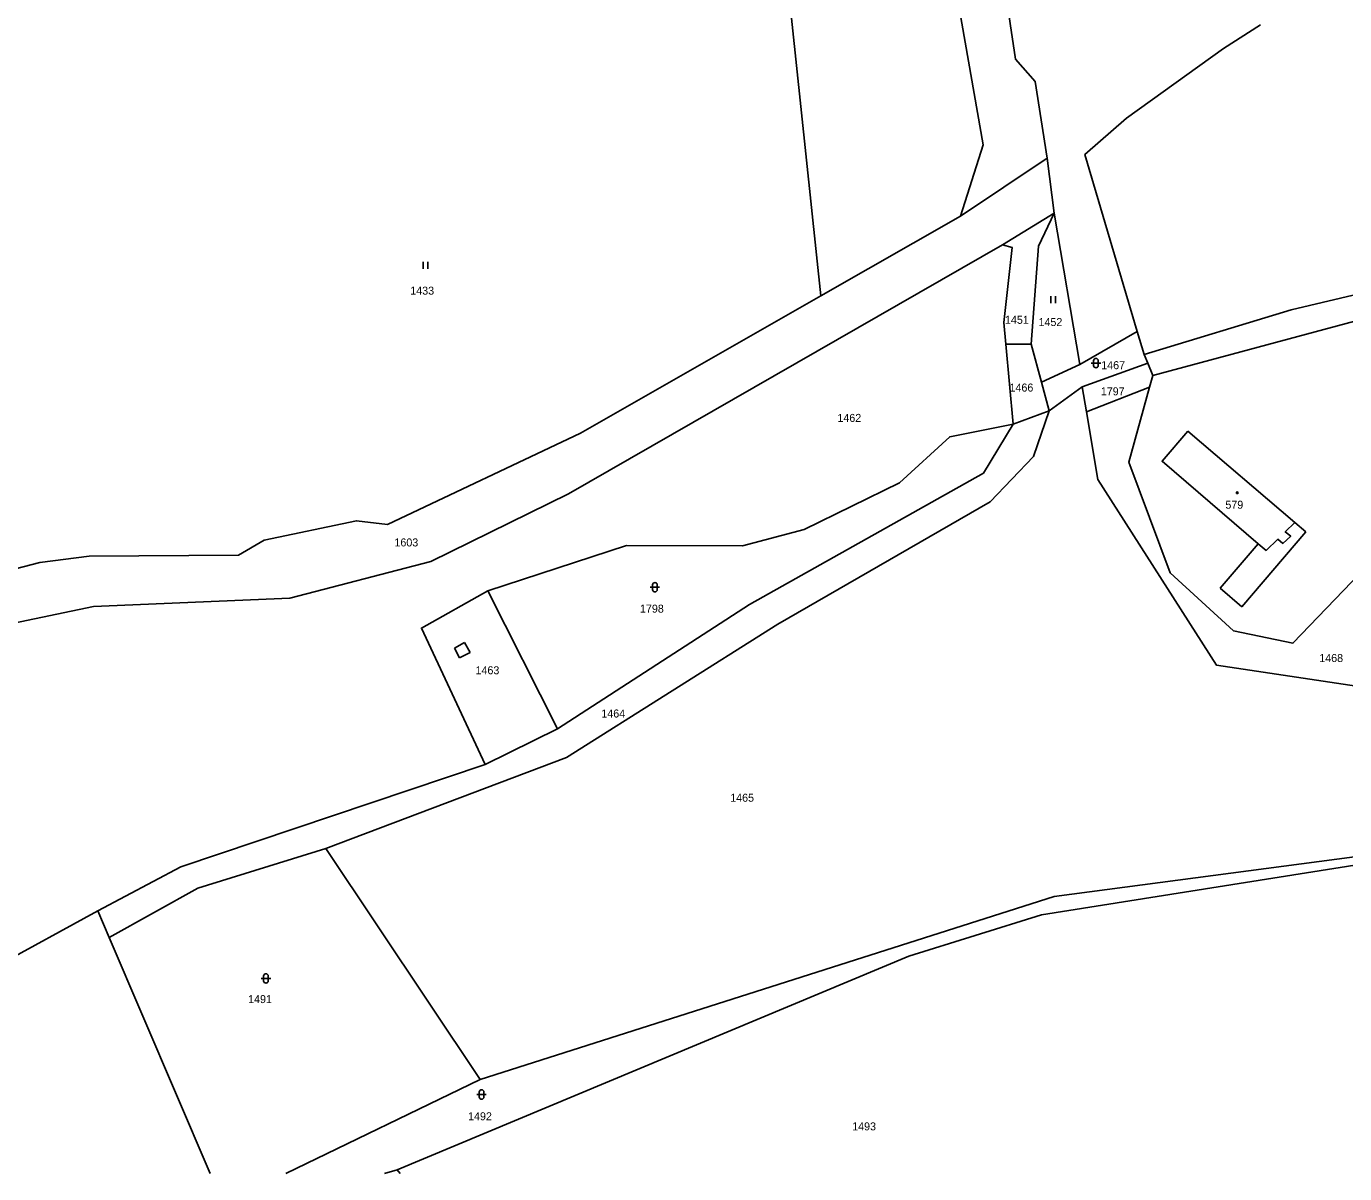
# Model space of a CAD drawing. Extents: x -520431 to -517205, y -1075927 to -1074013.
# Drawn here: x -518324.2 to -518044.1, y -1075925.4 to -1075681.5 of the extents above; entities that cross this region are included whole.
import ezdxf

# ---------------------------------------------------------------- set-up
doc = ezdxf.new("R2010")
doc.units = 0
for name, color, linetype in [('Hranice parcel', 7, 'Continuous'), ('Parcelní čísla', 7, 'Continuous'), ('Vnitřní kresba', 7, 'Continuous'), ('Značky budov', 7, 'Continuous'), ('Značky kultur', 7, 'Continuous')]:
    doc.layers.add(name, color=color, linetype=linetype)

msp = doc.modelspace()

# ---------------------------------------------------------------- linework, layer by layer
at = {"layer": 'Hranice parcel'}
for p, q in [((-518125.69, -1075721.88), (-518107.27, -1075709.57)), ((-518107.27, -1075709.57), (-518105.79, -1075721.22)), ((-518155.35, -1075738.81), (-518125.69, -1075721.88)), ((-518105.79, -1075721.22), (-518116.8, -1075727.96)), ((-518105.79, -1075721.22), (-518100.35, -1075753.39)), ((-518100.35, -1075753.39), (-518088.14, -1075746.39)), ((-518088.14, -1075746.39), (-518086.69, -1075751.28)), ((-518116.08, -1075749.11), (-518110.69, -1075749.06)), ((-518114.49, -1075766.06), (-518116.08, -1075749.11)), ((-518110.69, -1075749.06), (-518108.51, -1075757.18)), ((-518086.69, -1075751.28), (-518085.91, -1075753.13)), ((-518108.51, -1075757.18), (-518100.35, -1075753.39)), ((-518099.83, -1075758.13), (-518085.91, -1075753.13)), ((-518085.91, -1075753.13), (-518084.83, -1075755.71)), ((-518084.83, -1075755.71), (-518085.54, -1075758.24)), ((-518106.88, -1075763.27), (-518108.51, -1075757.18)), ((-518099.83, -1075758.13), (-518106.88, -1075763.27)), ((-518098.94, -1075763.48), (-518099.83, -1075758.13)), ((-518085.54, -1075758.24), (-518098.94, -1075763.48)), ((-518106.88, -1075763.27), (-518114.49, -1075766.06)), ((-518054.69, -1075786.96), (-518077.38, -1075767.59)), ((-518211.35, -1075830.82), (-518226.11, -1075801.52)), ((-518211.35, -1075830.82), (-518226.68, -1075838.43)), ((-518260.58, -1075856.25), (-518227.75, -1075905.32)), ((-518394.26, -1075915.99), (-518309, -1075869.51)), ((-518309, -1075869.51), (-518306.58, -1075875.18)), ((-518306.58, -1075875.18), (-518285.15, -1075925.35)), ((-518269.1, -1075925.35), (-518227.75, -1075905.32))]:
    msp.add_line(p, q, dxfattribs=at)
for points in [[(-518107.27, -1075709.57), (-518109.82, -1075693.22), (-518114.05, -1075688.54), (-518118.33, -1075659.57), (-518116.37, -1075640), (-518115.8, -1075620.46), (-518096.66, -1075553.44), (-518083.3, -1075495.38)], [(-518125.69, -1075721.88), (-518120.86, -1075706.74), (-518130.94, -1075649.23), (-518129.54, -1075625.65), (-518098.36, -1075508.57)], [(-518129.56, -1075514.81), (-518165.76, -1075640.85), (-518155.35, -1075738.81)], [(-518061.96, -1075681.23), (-518069.84, -1075686.25), (-518090.4, -1075701.07), (-518099.28, -1075708.75), (-518088.14, -1075746.39)], [(-518110.69, -1075749.06), (-518109.16, -1075728.24), (-518105.79, -1075721.22)], [(-518116.8, -1075727.96), (-518208.99, -1075780.87), (-518238.27, -1075795.25), (-518268.25, -1075803.04), (-518309.96, -1075804.85), (-518338.15, -1075810.74), (-518413.65, -1075837.42), (-518527.16, -1075889.45), (-518593.63, -1075918.35), (-518605.58, -1075925.35)], [(-518116.8, -1075727.96), (-518114.75, -1075728.5), (-518116.52, -1075744.49), (-518116.08, -1075749.11)], [(-518086.69, -1075751.28), (-518055.42, -1075741.77), (-518016.17, -1075732.51)], [(-517996.55, -1075735.82), (-518019.67, -1075739.43), (-518041.93, -1075744.18), (-518084.83, -1075755.71)], [(-518539.62, -1075883.42), (-518420.38, -1075829.77), (-518342.36, -1075800.93), (-518321.32, -1075795.48), (-518310.89, -1075794.16), (-518279.1, -1075793.91), (-518273.64, -1075790.72), (-518254.06, -1075786.62), (-518247.44, -1075787.39), (-518206.44, -1075767.96), (-518155.35, -1075738.81)], [(-518085.54, -1075758.24), (-518089.97, -1075774.12), (-518081.15, -1075797.65), (-518067.69, -1075810.01), (-518055.06, -1075812.63), (-518040.79, -1075797.74), (-518033, -1075822.13), (-518014.08, -1075819.78)], [(-518260.58, -1075856.25), (-518209.44, -1075836.89), (-518164.54, -1075808.55), (-518119.37, -1075782.61), (-518110.18, -1075772.93), (-518106.88, -1075763.27)], [(-518014.21, -1075822.61), (-518021.91, -1075823.46), (-518033.09, -1075823.04), (-518071.28, -1075817.31), (-518096.56, -1075777.81), (-518098.94, -1075763.48)], [(-518226.11, -1075801.52), (-518196.66, -1075791.85), (-518172.05, -1075791.94), (-518158.93, -1075788.49), (-518138.65, -1075778.54), (-518128, -1075768.76), (-518114.49, -1075766.06)], [(-518114.49, -1075766.06), (-518120.84, -1075776.47), (-518170.56, -1075804.39), (-518211.35, -1075830.82)], [(-518077.38, -1075767.59), (-518082.87, -1075773.97), (-518062.47, -1075791.52)], [(-518062.47, -1075791.52), (-518060.73, -1075792.9), (-518058.27, -1075790.54), (-518057.18, -1075791.41), (-518055.52, -1075789.9), (-518056.69, -1075788.96), (-518054.69, -1075786.96)], [(-518226.68, -1075838.43), (-518240.26, -1075809.42), (-518226.11, -1075801.52)], [(-518226.68, -1075838.43), (-518291.36, -1075860.15), (-518309, -1075869.51)], [(-518227.75, -1075905.32), (-518105.79, -1075866.49), (-518015.72, -1075854.53)], [(-518306.58, -1075875.18), (-518287.75, -1075864.69), (-518260.58, -1075856.25)], [(-518245.4, -1075924.54), (-518136.67, -1075879.16), (-518108.52, -1075870.36), (-518027.59, -1075857.54)], [(-518248.07, -1075925.35), (-518245.4, -1075924.54)], [(-518245.4, -1075924.54), (-518244.75, -1075925.35)]]:
    msp.add_lwpolyline(points, dxfattribs=at)
at = {"layer": 'Vnitřní kresba'}
for p, q in [((-518054.69, -1075786.96), (-518052.34, -1075788.97)), ((-518052.34, -1075788.97), (-518065.91, -1075804.93)), ((-518070.56, -1075800.92), (-518062.47, -1075791.52)), ((-518065.91, -1075804.93), (-518070.56, -1075800.92)), ((-518233.23, -1075813.7), (-518231.12, -1075812.46)), ((-518231.12, -1075812.46), (-518229.9, -1075814.63)), ((-518232.13, -1075815.77), (-518233.23, -1075813.7)), ((-518229.9, -1075814.63), (-518232.13, -1075815.77))]:
    msp.add_line(p, q, dxfattribs=at)
at = {"layer": 'Značky budov'}
msp.add_circle((-518066.91, -1075780.66), 0.175, dxfattribs=at)
at = {"layer": 'Značky kultur'}
for p, q in [((-518239.92, -1075733.07), (-518239.92, -1075731.57)), ((-518238.92, -1075733.07), (-518238.92, -1075731.57)), ((-518106.54, -1075740.37), (-518106.54, -1075738.87)), ((-518105.54, -1075740.37), (-518105.54, -1075738.87)), ((-518097.92, -1075753.1), (-518095.92, -1075753.1)), ((-518097.42, -1075752.6), (-518097.42, -1075753.6)), ((-518096.42, -1075753.6), (-518096.42, -1075752.6)), ((-518191.64, -1075800.74), (-518189.64, -1075800.74)), ((-518191.14, -1075800.24), (-518191.14, -1075801.24)), ((-518190.14, -1075801.24), (-518190.14, -1075800.24)), ((-518274.29, -1075883.87), (-518272.29, -1075883.87)), ((-518273.79, -1075883.37), (-518273.79, -1075884.37)), ((-518272.79, -1075884.37), (-518272.79, -1075883.37)), ((-518227.97, -1075908.04), (-518227.97, -1075909.04)), ((-518226.97, -1075909.04), (-518226.97, -1075908.04)), ((-518228.47, -1075908.54), (-518226.47, -1075908.54))]:
    msp.add_line(p, q, dxfattribs=at)
for centre, start, end in [((-518096.92, -1075752.6), 0, 180), ((-518096.92, -1075753.6), 180, 359.9879), ((-518190.64, -1075800.24), 0, 180), ((-518190.64, -1075801.24), 180, 359.9879), ((-518273.29, -1075883.37), 0, 180), ((-518273.29, -1075884.37), 180, 359.9879), ((-518227.47, -1075908.04), 0, 180), ((-518227.47, -1075909.04), 180, 359.9879)]:
    msp.add_arc(centre, 0.5, start, end, dxfattribs=at)

# ---------------------------------------------------------------- texts
at = {"layer": 'Parcelní čísla'}
for s, p in [('1433', (-518242.62, -1075738.55)), ('1451', (-518116.26, -1075744.75)), ('1452', (-518109.13, -1075745.23)), ('1467', (-518095.8, -1075754.39)), ('1466', (-518115.29, -1075759.15)), ('1797', (-518095.89, -1075759.95)), ('1462', (-518151.86, -1075765.6)), ('579', (-518069.42, -1075784.05)), ('1603', (-518245.99, -1075792.06)), ('1798', (-518193.81, -1075806.13)), ('1468', (-518049.47, -1075816.63)), ('1463', (-518228.76, -1075819.23)), ('1464', (-518202.02, -1075828.42)), ('1465', (-518174.64, -1075846.32)), ('1491', (-518277.08, -1075889.11)), ('1492', (-518230.34, -1075914.01)), ('1493', (-518148.72, -1075916.16))]:
    msp.add_text(s, height=1.7, dxfattribs=at).set_placement(p)

doc.saveas('drawing.dxf')
